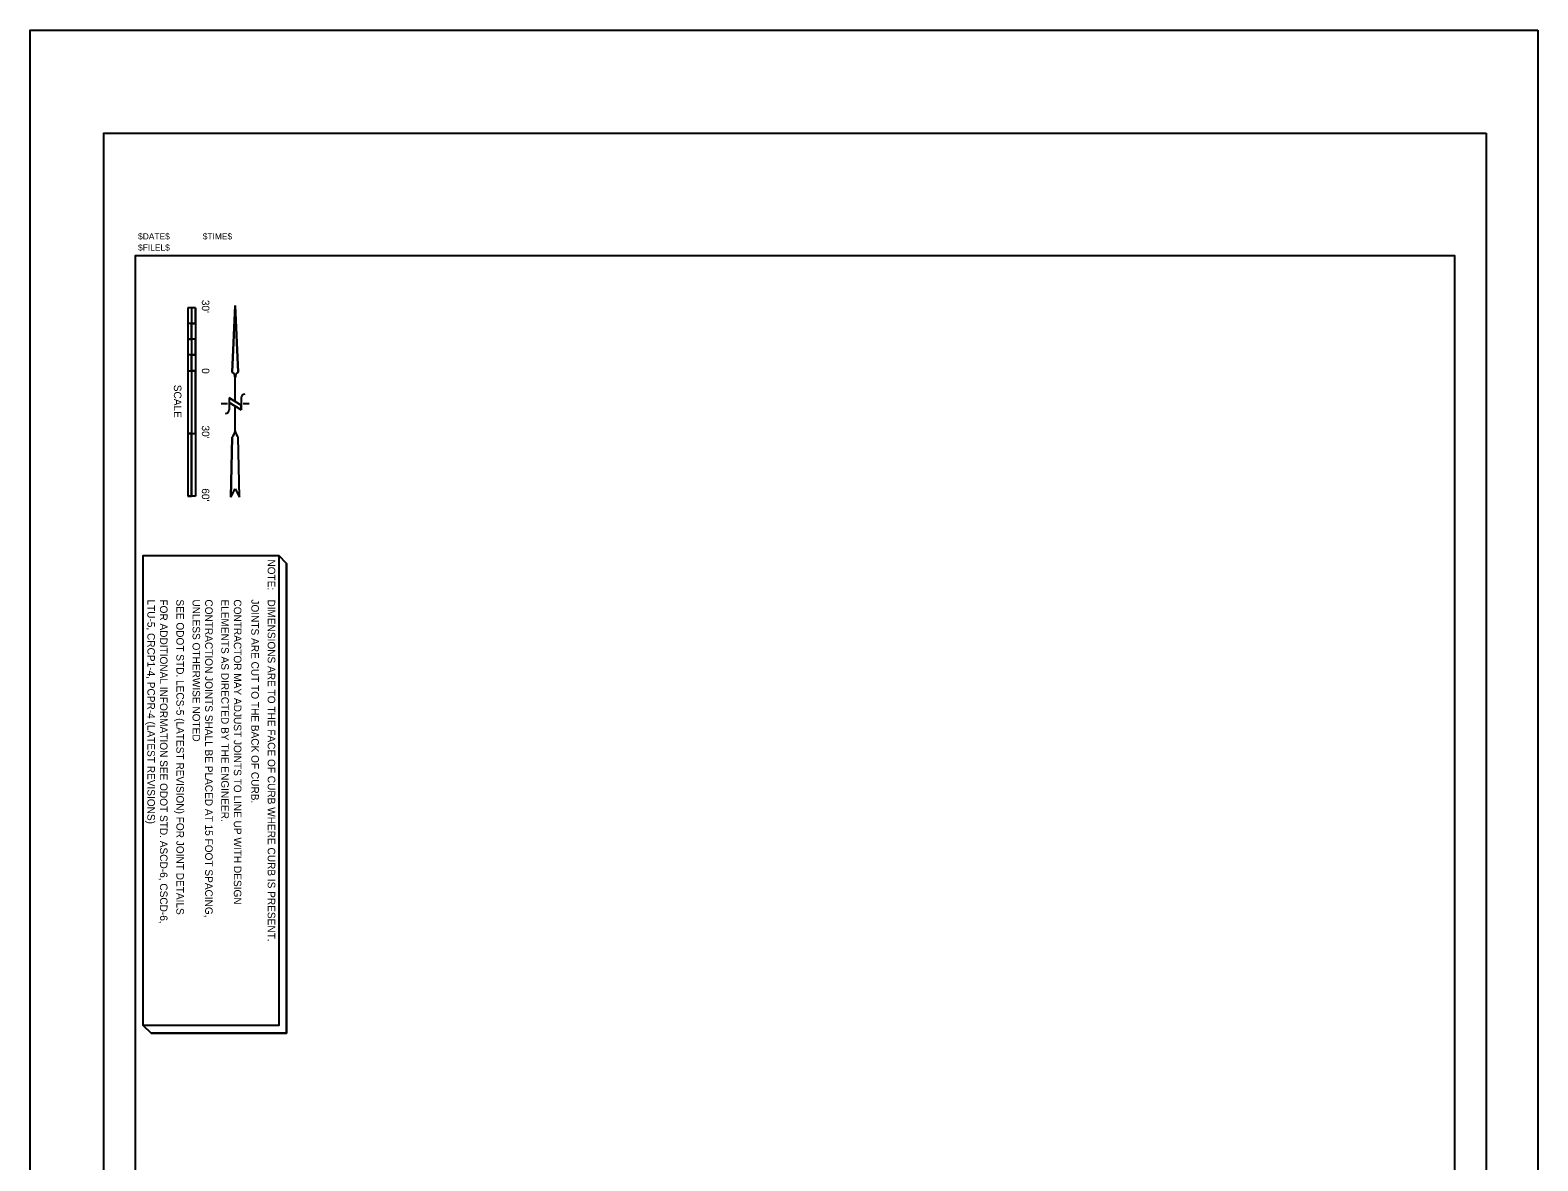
# Model space of a CAD drawing. Extents: x 2150474 to 2151194, y 145574 to 146654.
# Drawn here: x 2150474 to 2151194, y 146114 to 146654 of the extents above; entities that cross this region are included whole.
import ezdxf

# ---------------------------------------------------------------- set-up
doc = ezdxf.new("R2010")
doc.units = 0
for name, color, linetype in [('PR_Shading_1', 7, 'Continuous'), ('PR_Txt', 7, 'Continuous'), ('SHT_North_Arrow', 7, 'Continuous'), ('SHT_Plot_Shape_Full', 7, 'Continuous'), ('SHT_Plot_Shape_Half', 7, 'Continuous'), ('SHT_Plot_Stamp', 7, 'Continuous'), ('SHT_Scale', 7, 'Continuous'), ('SHT_Sheet_Border', 7, 'Continuous')]:
    doc.layers.add(name, color=color, linetype=linetype)

msp = doc.modelspace()

# ---------------------------------------------------------------- linework, layer by layer
at = {"layer": 'PR_Shading_1'}
msp.add_line((2150596.09, 146399.1), (2150592.34, 146402.85), dxfattribs=at)
for points in [[(2150592.34, 146402.85), (2150592.34, 146178.43), (2150527.66, 146178.43)], [(2150527.66, 146178.43), (2150531.41, 146174.68), (2150596.09, 146174.68), (2150596.09, 146399.1)]]:
    msp.add_lwpolyline(points, dxfattribs=at)
at = {"layer": 'PR_Txt'}
msp.add_lwpolyline([(2150592.34, 146402.85), (2150592.34, 146178.43), (2150527.66, 146178.43), (2150527.66, 146402.85)], close=True, dxfattribs=at)
msp.add_lwpolyline([(2150592.34, 146402.85), (2150596.09, 146399.1), (2150596.09, 146174.68), (2150531.41, 146174.68), (2150527.66, 146178.43)], dxfattribs=at)
at = {"layer": 'SHT_North_Arrow'}
for p, q in [((2150570.1, 146490.46), (2150571.54, 146522.2)), ((2150571.54, 146522.2), (2150570.1, 146490.46)), ((2150571.54, 146522.2), (2150572.98, 146490.46)), ((2150572.98, 146490.46), (2150571.54, 146522.2)), ((2150571.54, 146476.43), (2150571.54, 146487.66)), ((2150574.42, 146474.7), (2150568.66, 146478.16)), ((2150568.66, 146478.16), (2150574.42, 146474.7)), ((2150568.66, 146478.16), (2150568.66, 146472.4)), ((2150571.54, 146476.43), (2150568.66, 146478.16)), ((2150568.66, 146478.16), (2150568.66, 146475.86)), ((2150574.42, 146478.16), (2150574.42, 146472.4)), ((2150567.8, 146475.28), (2150564.92, 146475.28)), ((2150574.42, 146472.4), (2150568.66, 146475.86)), ((2150574.42, 146474.7), (2150571.54, 146476.43)), ((2150571.54, 146462.33), (2150571.54, 146474.13)), ((2150574.42, 146472.4), (2150574.42, 146474.7)), ((2150578.16, 146475.28), (2150575.28, 146475.28)), ((2150569.53, 146430.66), (2150570.1, 146459.45)), ((2150570.1, 146459.45), (2150569.53, 146430.66)), ((2150573.56, 146430.66), (2150572.98, 146459.45)), ((2150573.56, 146430.66), (2150572.98, 146459.45)), ((2150569.53, 146430.66), (2150571.54, 146434.69)), ((2150569.53, 146430.66), (2150571.54, 146434.69)), ((2150571.54, 146434.69), (2150573.56, 146430.66)), ((2150571.54, 146434.69), (2150573.56, 146430.66))]:
    msp.add_line(p, q, dxfattribs=at)
for points in [[(2150568.66, 146475.86), (2150571.54, 146474.13), (2150574.42, 146472.4)], [(2150571.54, 146462.33), (2150571.54, 146462.33), (2150571.54, 146462.33)]]:
    msp.add_lwpolyline(points, dxfattribs=at)
for centre, radius, start, end in [((2150568.09, 146487.66), 3.45, 360, 54.38016), ((2150568.09, 146487.66), 3.45, 360, 54.38016), ((2150574.99, 146487.66), 3.45, 125.61984, 180), ((2150574.99, 146487.66), 3.45, 125.61984, 180), ((2150576.15, 146478.16), 1.73, 90, 180), ((2150566.93, 146472.4), 1.73, 270, 0), ((2150566.53, 146463.03), 5.06, 314.95671, 352.41889), ((2150566.53, 146463.03), 5.06, 314.95671, 352.059), ((2150576.55, 146463.03), 5.06, 187.58111, 225.04329), ((2150576.55, 146463.03), 5.06, 187.941, 225.04329)]:
    msp.add_arc(centre, radius, start, end, dxfattribs=at)
at = {"layer": 'SHT_Plot_Shape_Full'}
msp.add_lwpolyline([(2151193.63, 146653.76), (2151193.63, 145573.76), (2150473.63, 145573.76), (2150473.63, 146653.76)], close=True, dxfattribs=at)
at = {"layer": 'SHT_Plot_Shape_Half'}
msp.add_lwpolyline([(2151168.88, 146604.63), (2151168.88, 145584.63), (2150508.88, 145584.63), (2150508.88, 146604.63)], close=True, dxfattribs=at)
at = {"layer": 'SHT_Scale'}
for p, q in [((2150552.63, 146521.13), (2150548.88, 146521.13)), ((2150548.88, 146521.13), (2150548.88, 146431.13)), ((2150550.76, 146521.13), (2150550.76, 146513.63)), ((2150552.63, 146521.13), (2150550.76, 146521.13)), ((2150550.76, 146521.13), (2150550.76, 146513.63)), ((2150552.63, 146521.13), (2150552.63, 146431.13)), ((2150552.63, 146513.63), (2150552.63, 146521.13)), ((2150552.63, 146513.63), (2150548.88, 146513.63)), ((2150550.76, 146513.63), (2150548.88, 146513.63)), ((2150548.88, 146513.63), (2150548.88, 146506.13)), ((2150550.76, 146513.63), (2150550.76, 146506.13)), ((2150550.76, 146513.63), (2150552.63, 146513.63)), ((2150550.76, 146506.13), (2150550.76, 146513.63)), ((2150552.63, 146506.13), (2150548.88, 146506.13)), ((2150552.63, 146506.13), (2150548.88, 146506.13)), ((2150548.88, 146506.13), (2150550.76, 146506.13)), ((2150550.76, 146506.13), (2150550.76, 146498.63)), ((2150552.63, 146506.13), (2150550.76, 146506.13)), ((2150550.76, 146506.13), (2150550.76, 146498.63)), ((2150552.63, 146498.63), (2150552.63, 146506.13)), ((2150552.63, 146498.63), (2150548.88, 146498.63)), ((2150550.76, 146498.63), (2150548.88, 146498.63)), ((2150548.88, 146498.63), (2150548.88, 146491.13)), ((2150550.76, 146498.63), (2150550.76, 146491.13)), ((2150550.76, 146498.63), (2150552.63, 146498.63)), ((2150550.76, 146491.13), (2150550.76, 146498.63)), ((2150548.88, 146491.13), (2150550.76, 146491.13)), ((2150548.88, 146491.13), (2150550.76, 146491.13)), ((2150550.76, 146491.13), (2150552.63, 146491.13)), ((2150550.76, 146491.13), (2150550.76, 146431.13)), ((2150552.63, 146491.13), (2150550.76, 146491.13)), ((2150550.76, 146491.13), (2150550.76, 146461.13)), ((2150552.63, 146461.13), (2150552.63, 146491.13)), ((2150548.88, 146461.13), (2150550.76, 146461.13)), ((2150550.76, 146461.13), (2150548.88, 146461.13)), ((2150548.88, 146461.13), (2150548.88, 146431.13)), ((2150550.76, 146461.13), (2150552.63, 146461.13)), ((2150550.76, 146461.13), (2150552.63, 146461.13)), ((2150550.76, 146431.13), (2150550.76, 146461.13)), ((2150550.76, 146431.13), (2150548.88, 146431.13)), ((2150548.88, 146431.13), (2150550.76, 146431.13)), ((2150552.63, 146431.13), (2150550.76, 146431.13))]:
    msp.add_line(p, q, dxfattribs=at)
at = {"layer": 'SHT_Sheet_Border'}
msp.add_lwpolyline([(2150523.88, 145601.13), (2150523.88, 146546.13), (2151153.88, 146546.13), (2151153.88, 145601.13)], close=True, dxfattribs=at)

# ---------------------------------------------------------------- texts
at = {"layer": 'PR_Txt'}
for s, p in [('NOTE:', (2150587.08, 146401)), ('LTU-5, CRCP1-4, PCPR-4 (LATEST REVISIONS)', (2150529.62, 146381.89)), ('FOR ADDITIONAL INFORMATION SEE ODOT STD. ASCD-6, CSCD-6,', (2150535.63, 146381.89)), ('SEE ODOT STD. LECS-5 (LATEST REVISION) FOR JOINT DETAILS', (2150543.47, 146381.89)), ('UNLESS OTHERWISE NOTED', (2150551.19, 146381.89)), ('CONTRACTION JOINTS SHALL BE PLACED AT 15 FOOT SPACING,', (2150557.2, 146381.89)), ('ELEMENTS AS DIRECTED BY THE ENGINEER.', (2150564.9, 146381.89)), ('CONTRACTOR MAY ADJUST JOINTS TO LINE UP WITH DESIGN', (2150570.91, 146381.89)), ('JOINTS ARE CUT TO THE BACK OF CURB.', (2150579.25, 146381.89)), ('DIMENSIONS ARE TO THE FACE OF CURB WHERE CURB IS PRESENT.', (2150587.08, 146381.89))]:
    msp.add_text(s, height=3.6, rotation=270, dxfattribs=at).set_placement(p)
at = {"layer": 'SHT_Plot_Stamp'}
for s, p in [('$DATE$', (2150525.16, 146553.78)), ('$TIME$', (2150556.05, 146553.78)), ('$FILEL$', (2150525.16, 146548.45))]:
    msp.add_text(s, height=3, rotation=360, dxfattribs=at).set_placement(p)
at = {"layer": 'SHT_Scale'}
for s, p in [("30'", (2150555.63, 146524.95)), ('0', (2150555.63, 146492.32)), ('SCALE', (2150542.28, 146484.39)), ("30'", (2150555.63, 146464.95)), ("60'", (2150555.63, 146434.95))]:
    msp.add_text(s, height=3.6, rotation=270, dxfattribs=at).set_placement(p)

doc.saveas('drawing.dxf')
